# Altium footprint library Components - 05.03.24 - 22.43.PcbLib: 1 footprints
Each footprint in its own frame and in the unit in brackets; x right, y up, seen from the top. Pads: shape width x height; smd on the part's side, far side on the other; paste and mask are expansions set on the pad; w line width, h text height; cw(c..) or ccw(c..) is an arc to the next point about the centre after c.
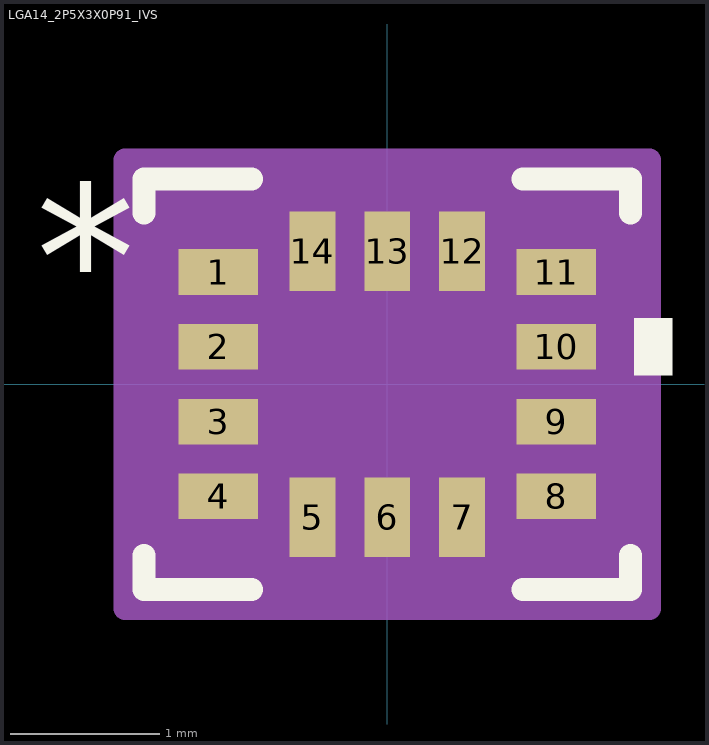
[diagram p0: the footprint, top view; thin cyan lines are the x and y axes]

## LGA14_2P5X3X0P91_IVS [mil]
pads (14):
  rect 21x12 smd paste+0 mask+0: 1(-44.5,29.53) 2(-44.5,9.84) 3(-44.5,-9.84) 4(-44.5,-29.53) 8(44.5,-29.53) 9(44.5,-9.84) 10(44.5,9.84) 11(44.5,29.53)
  rect 12x21 smd paste+0 mask+0: 5(-19.68,-35) 6(0,-35) 7(19.68,-35) 12(19.68,35) 13(0,35) 14(-19.68,35)
Top Overlay:
  region: 65,17.34 75,17.34 75,2.34 65,2.34
  lines w6: -64,-45.05 -64,-54 -35.65,-54 ; -64,45.05 -64,54 -35.65,54 ; 35.65,-54 64,-54 64,-45.05 ; 35.65,54 64,54 64,45.05
  text "*" at -92.5,14.37 h50
Mechanical 13:
  lines w1: -59,-1 -9,49 ; -59,-49 -59,49 59,49 59,-49 -59,-49 ; -59,-35.53 -55,-35.53 -55,-23.53 -59,-23.53 -59,-35.53 ; -59,-15.84 -55,-15.84 -55,-3.84 -59,-3.84 -59,-15.84 ; -59,3.84 -55,3.84 -55,15.84 -59,15.84 -59,3.84 ; -59,23.53 -55,23.53 -55,35.53 -59,35.53 -59,23.53 ; -25.68,-49 -25.68,-45.5 -13.69,-45.5 -13.69,-49 -25.68,-49 ; -25.68,45.5 -25.68,49 -13.69,49 -13.69,45.5 -25.68,45.5 ; -6,-49 -6,-45.5 6,-45.5 6,-49 -6,-49 ; -6,45.5 -6,49 6,49 6,45.5 -6,45.5 ; 13.69,-49 13.69,-45.5 25.68,-45.5 25.68,-49 13.69,-49 ; 13.69,45.5 13.69,49 25.68,49 25.68,45.5 13.69,45.5 ; 55,-35.53 55,-23.53 59,-23.53 59,-35.53 55,-35.53 ; 55,-15.84 55,-3.84 59,-3.84 59,-15.84 55,-15.84 ; 55,3.84 55,15.84 59,15.84 59,3.84 55,3.84 ; 55,23.53 55,35.53 59,35.53 59,23.53 55,23.53
  text "*" at -46.5,14.37 h50
Mechanical 15:
  region: -35.69,-59 -69,-59 -69,-45.53 -69,45.53 -69,59 -35.69,59 35.69,59 69,59 69,45.53 69,-45.53 69,-59 35.69,-59
  lines w6: -69,-59 -35.69,-59 35.69,-59 69,-59 69,-45.53 69,45.53 69,59 35.69,59 -35.69,59 -69,59 -69,45.53 -69,-45.53 -69,-59
3D body "LGA14_2P5X3X0P91_IVS.step": height 38.11, standoff 0, extent -59.02,-49.02 59.02,49.02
